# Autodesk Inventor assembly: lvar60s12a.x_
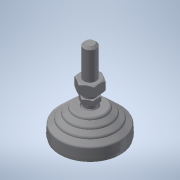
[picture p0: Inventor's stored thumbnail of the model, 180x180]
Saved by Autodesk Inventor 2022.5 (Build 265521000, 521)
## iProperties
Part Number: lvar60s12a.x_
Material: 一般
Document SubType Name: Assembly
Designer: ImaoCorp
Sending System: SOLIDWORKS 2017-2017317
MC: AMD64
MC_MODEL: Intel64 Family 6 Model 60 Stepping 3, GenuineIntel
OS: Windows_NT
FRU: Parasolid Version 29.0, build 201,  4-17-2017
FORMAT: text
GUISE: transmit
KEY: lvar60s12a
FILE: lvar60s12a.x_t
DATE: Mon Jul 01 18:12:49 2019
Author: ImaoCorp
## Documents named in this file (3)
- X:\14_SW2022-Inv2022\00_全2023-1023新製品(TCC)まで\l\lvar60s12a\LVAR60S12A.iam
- X:\14_SW2022-Inv2022\00_全2023-1023新製品(TCC)まで\l\lvar60s12a\lvar60s12a_01.ipt
- X:\14_SW2022-Inv2022\00_全2023-1023新製品(TCC)まで\l\lvar60s12a\lvar60s12a_02.ipt
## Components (2 placed, 2 different names)
1. lvar60s12a_01
2. lvar60s12a_02
